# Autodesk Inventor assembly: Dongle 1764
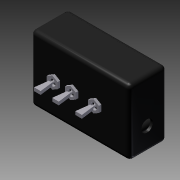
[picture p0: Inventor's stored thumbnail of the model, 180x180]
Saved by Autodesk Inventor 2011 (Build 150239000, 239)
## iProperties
Created: 2010-01
Part Number: Dongle 1764
Document SubType Name: Weldment
Designer: jgehrig
Weld Material: Welded Aluminum-6061
Author: jgehrig
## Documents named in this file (7)
- R:\CAD Archives\Electronics\Dongle 1764\Dongle 1764.iam
- R:\CAD Archives\Electronics\Dongle 1764\Dongle Base 1764.ipt
- R:\CAD Archives\Electronics\Dongle 1764\DongleTop 1764.ipt
- R:\CAD Archives\Electronics\Dongle 1764\Dongle switch 1764.ipt
- R:\CAD Archives\Electronics\Dongle 1764\Dongle Hexagon 1764.ipt
- R:\CAD Archives\Electronics\Dongle 1764\Dongle Flat 1764.ipt
- R:\CAD Archives\Electronics\Dongle 1764\Dongle Blue Box 1764.ipt
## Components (20 placed, 6 different names)
1. Dongle Base 1764:1 — Mate:1, Mate:2, Angle:1, Mate:3, Mate:4, Mate:5, Mate:6, Mate:7, Mate:8, Angle:4, Mate:9, Mate:10, Mate:11, Mate:12, Mate:33, Mate:34, Mate:35
2. Dongle Blue Box 1764:1 — Mate:23, Flush:11, Flush:12, Flush:15, Mate:24, Flush:16, Mate:25, Mate:26
3. Dongle Blue Box 1764:2 — Mate:18, Flush:6, Flush:7, Mate:19, Flush:8, Flush:9, Mate:20, Mate:22
4. Dongle Blue Box 1764:3 — Mate:13, Flush:1, Flush:2, Mate:14, Flush:3, Flush:4, Mate:17, Mate:21
5. Dongle Flat 1764:1 — Flush:15, Mate:24, Flush:16
6. Dongle Flat 1764:2 — Mate:23, Flush:11, Flush:12, Flush:17
7. Dongle Flat 1764:3 — Mate:19, Flush:8, Flush:9, Flush:10
8. Dongle Flat 1764:4 — Mate:18, Flush:6, Flush:7
9. Dongle Flat 1764:5 — Mate:14, Flush:3, Flush:4, Flush:5
10. Dongle Flat 1764:6 — Mate:13, Flush:1, Flush:2
11. Dongle Hexagon 1764:1 — Mate:1, Mate:2, Angle:1, Angle:2, Mate:31, Mate:32, Angle:9
12. Dongle Hexagon 1764:2 — Mate:9, Mate:10, Angle:5, Mate:17, Flush:5, Mate:21
13. Dongle Hexagon 1764:3 — Mate:7, Mate:8, Angle:4, Angle:5, Angle:6, Mate:20, Flush:10, Mate:22
14. Dongle Hexagon 1764:4 — Mate:5, Mate:6, Angle:3, Mate:27, Mate:28, Angle:7
15. Dongle Hexagon 1764:5 — Mate:3, Mate:4, Angle:2, Angle:3, Mate:29, Mate:30, Angle:8
16. Dongle Hexagon 1764:6 — Mate:11, Mate:12, Angle:6, Mate:25, Flush:17, Mate:26
17. Dongle Switch 1764:1 — Mate:31, Mate:32, Angle:9
18. Dongle Switch 1764:1 — Mate:27, Mate:28, Angle:7
19. Dongle Switch 1764:1 — Mate:29, Mate:30, Angle:8
20. DongleTop 1764:1 — Mate:33, Mate:34, Mate:35
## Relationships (57: Mate 33, Flush 15, Angle 9)
- Mate:1: Dongle Base 1764:1 ↔ Dongle Hexagon 1764:1
- Mate:2: Dongle Base 1764:1 ↔ Dongle Hexagon 1764:1
- Angle:1: Dongle Base 1764:1 ↔ Dongle Hexagon 1764:1
- Mate:3: Dongle Base 1764:1 ↔ Dongle Hexagon 1764:5
- Mate:4: Dongle Base 1764:1 ↔ Dongle Hexagon 1764:5
- Angle:2: Dongle Hexagon 1764:1 ↔ Dongle Hexagon 1764:5
- Mate:5: Dongle Base 1764:1 ↔ Dongle Hexagon 1764:4
- Mate:6: Dongle Base 1764:1 ↔ Dongle Hexagon 1764:4
- Angle:3: Dongle Hexagon 1764:4 ↔ Dongle Hexagon 1764:5
- Mate:7: Dongle Base 1764:1 ↔ Dongle Hexagon 1764:3
- Mate:8: Dongle Base 1764:1 ↔ Dongle Hexagon 1764:3
- Angle:4: Dongle Base 1764:1 ↔ Dongle Hexagon 1764:3
- Mate:9: Dongle Base 1764:1 ↔ Dongle Hexagon 1764:2
- Mate:10: Dongle Base 1764:1 ↔ Dongle Hexagon 1764:2
- Angle:5: Dongle Hexagon 1764:2 ↔ Dongle Hexagon 1764:3
- Mate:11: Dongle Base 1764:1 ↔ Dongle Hexagon 1764:6
- Mate:12: Dongle Base 1764:1 ↔ Dongle Hexagon 1764:6
- Angle:6: Dongle Hexagon 1764:3 ↔ Dongle Hexagon 1764:6
- Mate:13: Dongle Blue Box 1764:3 ↔ Dongle Flat 1764:6
- Flush:1: Dongle Blue Box 1764:3 ↔ Dongle Flat 1764:6
- Flush:2: Dongle Blue Box 1764:3 ↔ Dongle Flat 1764:6
- Mate:14: Dongle Blue Box 1764:3 ↔ Dongle Flat 1764:5
- Flush:3: Dongle Blue Box 1764:3 ↔ Dongle Flat 1764:5
- Flush:4: Dongle Blue Box 1764:3 ↔ Dongle Flat 1764:5
- Mate:17: Dongle Blue Box 1764:3 ↔ Dongle Hexagon 1764:2
- Flush:5: Dongle Flat 1764:5 ↔ Dongle Hexagon 1764:2
- Mate:18: Dongle Blue Box 1764:2 ↔ Dongle Flat 1764:4
- Flush:6: Dongle Blue Box 1764:2 ↔ Dongle Flat 1764:4
- Flush:7: Dongle Blue Box 1764:2 ↔ Dongle Flat 1764:4
- Mate:19: Dongle Blue Box 1764:2 ↔ Dongle Flat 1764:3
- Flush:8: Dongle Blue Box 1764:2 ↔ Dongle Flat 1764:3
- Flush:9: Dongle Blue Box 1764:2 ↔ Dongle Flat 1764:3
- Mate:20: Dongle Blue Box 1764:2 ↔ Dongle Hexagon 1764:3
- Flush:10: Dongle Flat 1764:3 ↔ Dongle Hexagon 1764:3
- Mate:21: Dongle Blue Box 1764:3 ↔ Dongle Hexagon 1764:2
- Mate:22: Dongle Blue Box 1764:2 ↔ Dongle Hexagon 1764:3
- Mate:23: Dongle Blue Box 1764:1 ↔ Dongle Flat 1764:2
- Flush:11: Dongle Blue Box 1764:1 ↔ Dongle Flat 1764:2
- Flush:12: Dongle Blue Box 1764:1 ↔ Dongle Flat 1764:2
- Flush:15: Dongle Blue Box 1764:1 ↔ Dongle Flat 1764:1
- Mate:24: Dongle Blue Box 1764:1 ↔ Dongle Flat 1764:1
- Flush:16: Dongle Blue Box 1764:1 ↔ Dongle Flat 1764:1
- Mate:25: Dongle Blue Box 1764:1 ↔ Dongle Hexagon 1764:6
- Flush:17: Dongle Flat 1764:2 ↔ Dongle Hexagon 1764:6
- Mate:26: Dongle Blue Box 1764:1 ↔ Dongle Hexagon 1764:6
- Mate:27: Dongle Hexagon 1764:4 ↔ Dongle Switch 1764:1
- Mate:28: Dongle Hexagon 1764:4 ↔ Dongle Switch 1764:1
- Angle:7: Dongle Hexagon 1764:4 ↔ Dongle Switch 1764:1
- Mate:29: Dongle Hexagon 1764:5 ↔ Dongle Switch 1764:1
- Mate:30: Dongle Hexagon 1764:5 ↔ Dongle Switch 1764:1
- Angle:8: Dongle Hexagon 1764:5 ↔ Dongle Switch 1764:1
- Mate:31: Dongle Hexagon 1764:1 ↔ Dongle Switch 1764:1
- Mate:32: Dongle Hexagon 1764:1 ↔ Dongle Switch 1764:1
- Angle:9: Dongle Hexagon 1764:1 ↔ Dongle Switch 1764:1
- Mate:33: Dongle Base 1764:1 ↔ DongleTop 1764:1
- Mate:34: Dongle Base 1764:1 ↔ DongleTop 1764:1
- Mate:35: Dongle Base 1764:1 ↔ DongleTop 1764:1
